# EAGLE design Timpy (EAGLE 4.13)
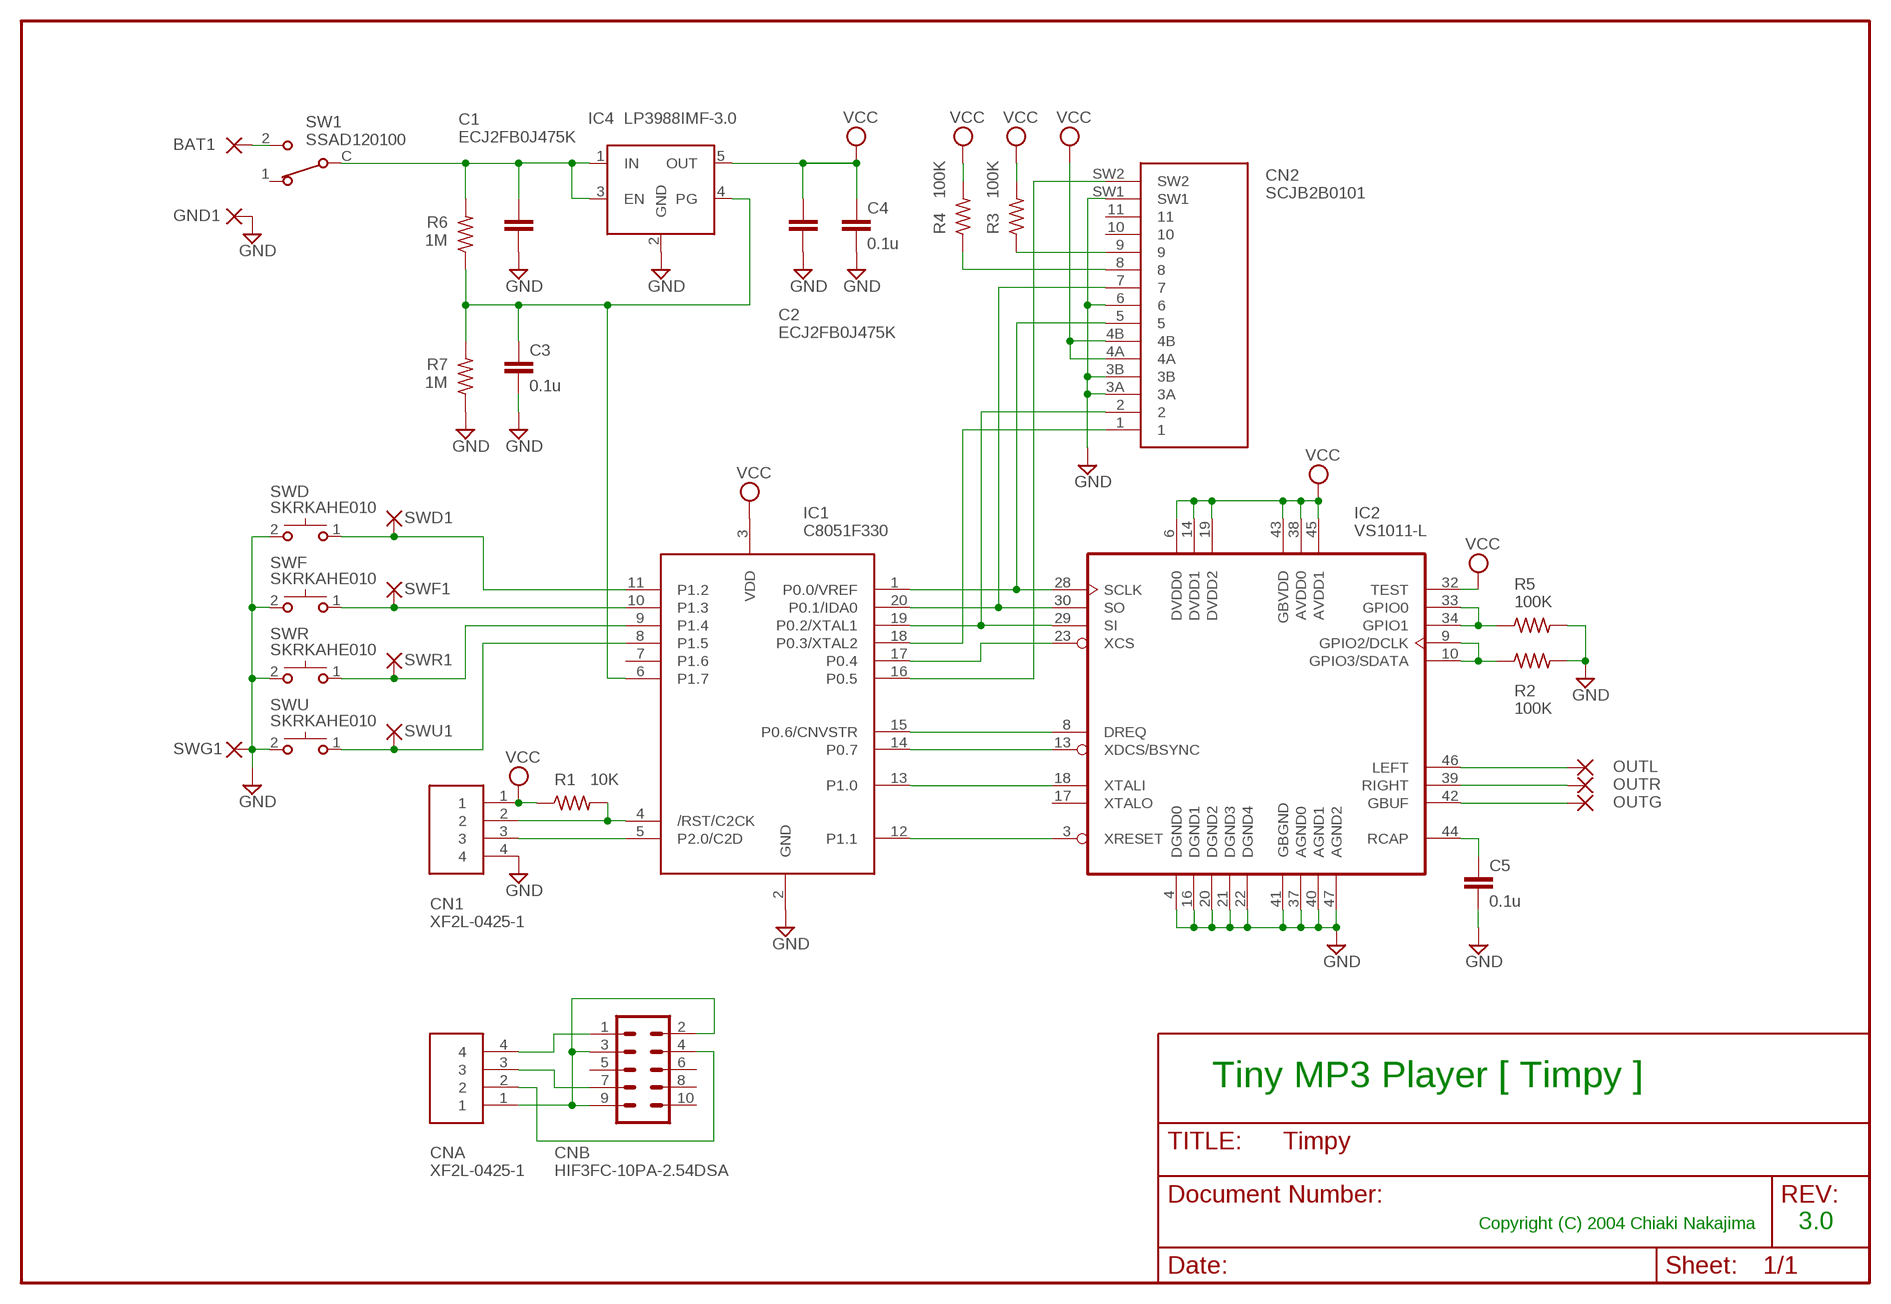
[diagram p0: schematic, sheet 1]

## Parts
BAT1  0.6/0.45  [0.6/0.45]
C1  ECJ2FB0J475K  C-EUC2012  [C2012]
C2  ECJ2FB0J475K  C-EUC2012  [C2012]
C3  0.1u  C-EUC1005  [C1005]
C4  0.1u  C-EUC1005  [C1005]
C5  0.1u  C-EUC1005  [C1005]
CN1  XF2L-0425-1  [XF2L-0425-1]
CN2  SCJB2B0101  SCJB2B010X  [SCJB2B010X]
CNA  XF2L-0425-1  [XF2L-0425-1]
CNB  HIF3FC-10PA-2.54DSA  ML10  [ML10]
GND1  0.6/0.45  [0.6/0.45]
IC1  C8051F330  C8051F33X-LARGE-PROTRUSION  [MLP20-LARGE-PROTRUSION]
IC2  VS1011-L  VS1011-LQFP48  [LQFP-48]
IC4  LP3988IMF-3.0  LP3988  [SOT23-5]
OUTG  0.6/0.45  [0.6/0.45]
OUTL  0.6/0.45  [0.6/0.45]
OUTR  0.6/0.45  [0.6/0.45]
R1  10K  R-US_R1005  [R1005]
R2  100K  R-US_R1005  [R1005]
R3  100K  R-US_R1005  [R1005]
R4  100K  R-US_R1005  [R1005]
R5  100K  R-US_R1005  [R1005]
R6  1M  R-US_R1005  [R1005]
R7  1M  R-US_R1005  [R1005]
SW1  SSAD120100  [SSAD120100]
SWD  SKRKAHE010  [SKRKAHE010]
SWD1  0.6/0.45  [0.6/0.45]
SWF  SKRKAHE010  [SKRKAHE010]
SWF1  0.6/0.45  [0.6/0.45]
SWG1  0.6/0.45  [0.6/0.45]
SWR  SKRKAHE010  [SKRKAHE010]
SWR1  0.6/0.45  [0.6/0.45]
SWU  SKRKAHE010  [SKRKAHE010]
SWU1  0.6/0.45  [0.6/0.45]

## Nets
BATTERY-PAD [Power]: BAT1.P$1(P) SW1.2
GND: C1.2 C2.2 C3.2 C4.2 C5.2 CN1.4 CN2.3A CN2.3B CN2.6 CN2.SW1 GND1.P$1(P) IC1.2(GND) IC2.4(DGND0) IC2.16(DGND1) IC2.20(DGND2) IC2.21(DGND3) IC2.22(DGND4) IC2.37(AGND0) IC2.40(AGND1) IC2.41(GBGND) IC2.47(AGND2) IC4.2(GND) R2.2 R5.2 R7.1 SWD.2 SWF.2 SWG1.P$1(P) SWR.2 SWU.2
N$1: CN1.3 IC1.5(P2.0/C2D)
N$2: IC1.8(P1.5) SWU1.P$1(P) SWU.1
N$3: CN1.2 IC1.4(/RST/C2CK) R1.2
N$4: CN2.9 R3.1
N$5: CN2.8 R4.1
N$6: CN2.5 IC1.1(P0.0/VREF) IC2.28(SCLK)
N$7: IC2.9(GPIO2/DCLK) IC2.10(GPIO3/SDATA) R2.1
N$8: CN2.7 IC1.20(P0.1/IDA0) IC2.30(SO)
N$9: CN2.2 IC1.19(P0.2/XTAL1) IC2.29(SI)
N$10: CN2.1 IC1.18(P0.3/XTAL2)
N$11: IC1.17(P0.4) IC2.23(XCS)
N$12: IC1.15(P0.6/CNVSTR) IC2.8(DREQ)
N$13: IC1.14(P0.7) IC2.13(XDCS/BSYNC)
N$14: IC1.13(P1.0) IC2.18(XTALI)
N$15: IC1.12(P1.1) IC2.3(XRESET)
N$16: IC2.33(GPIO0) IC2.34(GPIO1) R5.1
N$17 [Analog Out]: IC2.46(LEFT) OUTL.P$1(P)
N$18 [Analog Out]: IC2.39(RIGHT) OUTR.P$1(P)
N$19: C3.1 IC1.6(P1.7) IC4.4(PG) R6.1 R7.2
N$20: C5.1 IC2.44(RCAP)
N$21: CN2.SW2 IC1.16(P0.5)
N$22: C1.1 IC4.1(IN) IC4.3(EN) R6.2 SW1.C
N$23 [Analog Out]: IC2.42(GBUF) OUTG.P$1(P)
N$24: IC1.9(P1.4) SWR1.P$1(P) SWR.1
N$25: IC1.10(P1.3) SWF1.P$1(P) SWF.1
N$26: IC1.11(P1.2) SWD1.P$1(P) SWD.1
N$27: CNA.4 CNB.1
N$28: CNA.3 CNB.7
N$29: CNA.2 CNB.4
N$32: CNA.1 CNB.2 CNB.3 CNB.9
VCC: C2.1 C4.1 CN1.1 CN2.4A CN2.4B IC1.3(VDD) IC2.6(DVDD0) IC2.14(DVDD1) IC2.19(DVDD2) IC2.32(TEST) IC2.38(AVDD0) IC2.43(GBVDD) IC2.45(AVDD1) IC4.5(OUT) R1.1 R3.2 R4.2
Unconnected: CN2.10 CN2.11 CNB.5 CNB.6 CNB.8 CNB.10 IC1.7(P1.6) IC2.17(XTALO) SW1.1

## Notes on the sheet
- Tiny MP3 Player [ Timpy ]
- Copyright (C) 2004 Chiaki Nakajima | 3.0

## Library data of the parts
BAT1 GND1 OUTG OUTL OUTR SWD1 SWF1 SWG1 SWR1 SWU1 = pads:0.6/0.45: 0.6mm/0.45mm Through-Hole Pad
C1-C5 = rcl:C-EU: CAPACITOR, European symbol
CN1 CNA = conn-omron-xf2l:XF2L-0425-1: 4P
CN2 = conn-alps-miniSD:SCJB2B010X: SCJB2B0101/2 miniSD connector
CNB = con-harting-ml:ML10: HARTING
IC1 = cygnal_33x:C8051F33X-LARGE-PROTRUSION: Cygnal C8051F330/1 microcontroller with large protrusion pads (for hand soldering)
IC2 = vs10x1-lqfp:VS1011-LQFP48: VS1011 MP3 Decoder (LQFP-48)
IC4 = lp3988:LP3988: National Semiconductor LP3988 Jul 07, 2004 Chiaki Nakajima http://www.chiaki.cc chi@chiaki.cc
R1-R7 = rcl:R-US_: RESISTOR, American symbol
SW1 = switch-alps-tact:SSAD120100: Slide Switch SPDT SSAD120100
SWD SWF SWR SWU = switch-alps:SKRKAHE010: Tact Switch SKRKAHE010

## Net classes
0 default: width 0.15 mm
1 Analog Out: width 0.3 mm
2 Power: width 0.5 mm

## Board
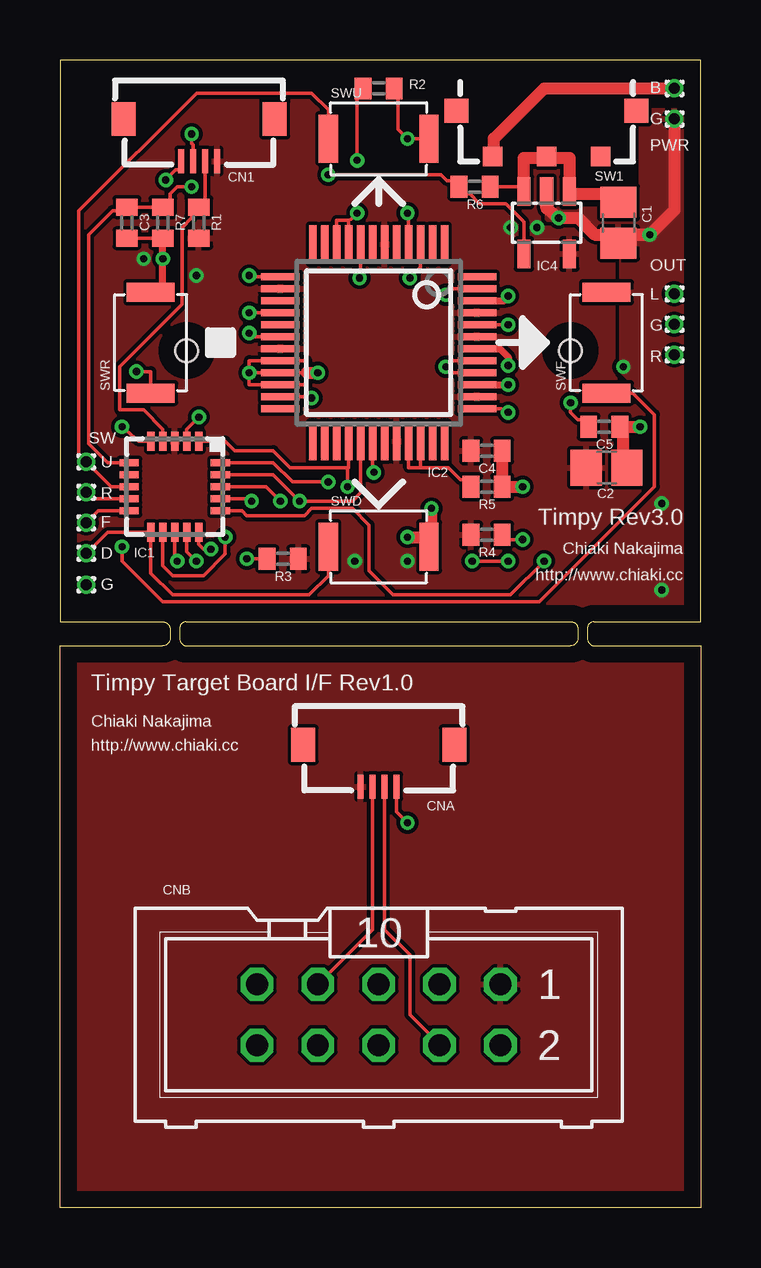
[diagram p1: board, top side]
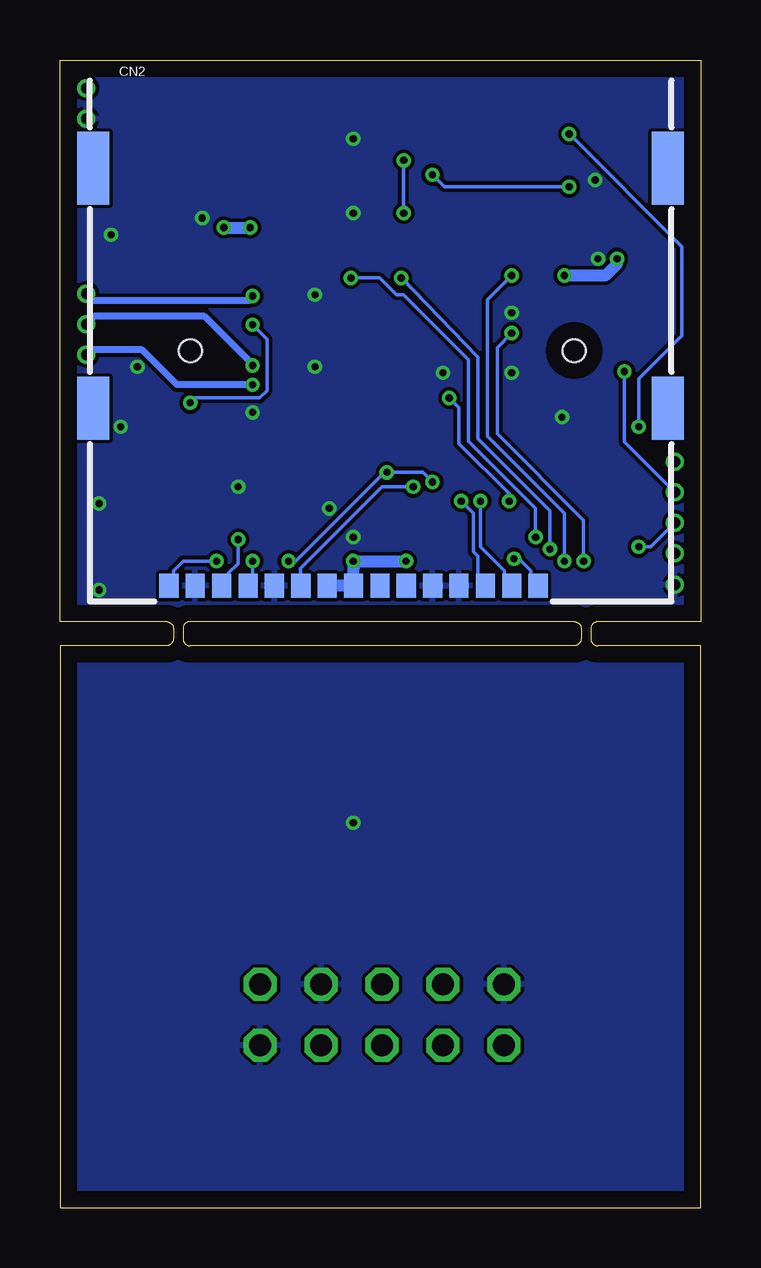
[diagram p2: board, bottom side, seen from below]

Size 26.72 x 47.82 mm. Coordinates in mm from the lower left corner, seen from the top.
Outline: 0,24.41 4.29,24.41 arc-90 4.59,24.11 4.59,23.71 arc-90 4.29,23.41 0,23.41 0,0 26.72,0 26.72,23.41 22.29,23.41 arc-90 21.99,23.71 21.99,24.14 arc-90 22.26,24.41 26.72,24.41 26.72,47.82 0,47.82 0,24.41
Outline: 5.29,23.41 21.29,23.41 arc90 21.59,23.71 21.59,24.14 arc90 21.32,24.41 5.26,24.41 arc90 4.99,24.14 4.99,23.71 arc90 5.29,23.41
Copper layers (1*16): Top 0.035mm / dielectric 1.5mm / Bottom 0.035mm
Design rules "p-ban_min": minimum track width 0.15mm, minimum drill 0.3mm, track to track 0.15mm, track to pad 0.15mm, pad to pad 0.15mm, via to via 0.15mm, smd to smd 0.15mm, copper to edge 0.7mm, drill to drill 0.45mm, minimum pad ring 0.15mm, minimum via ring 0.15mm, stop-mask expansion 4mil, vias tented up to drill 0mil, thermal gap 0.15mm

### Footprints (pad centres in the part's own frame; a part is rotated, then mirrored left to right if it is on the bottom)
0.6/0.45 = drill 0.45 pad 0.6 round: P$1 0,0
C2012 = smd 1.3 x 1.5: 1 -0.85,0; 2 0.85,0
C1005 = smd 0.7 x 0.9: 1 -0.65,0; 2 0.65,0
XF2L-0425-1 = smd 0.25 x 1: 1 -0.75,0.5; 2 -0.25,0.5; 3 0.25,0.5; 4 0.75,0.5 | smd 1 x 1.4: F1 -3.15,-1.25; F2 3.15,-1.25
SCJB2B010X = smd 0.8 x 1: 1 -6.35,0; 2 -5.25,0; 3A -4.15,0; 3B -3.05,0; 4A 0.25,0; 4B 1.35,0; 5 2.45,0; 6 3.55,0; 7 4.65,0; 8 5.75,0; 9 -7.45,0; 10 -1.95,0; 11 -0.85,0; SW1 6.85,0; SW2 7.95,0 | smd 1.35 x 2.6: F1 -12.85,-7.4; F2 11.1,-7.4 | smd 1.35 x 3: F3 -12.85,-17.4; F4 11.1,-17.4 | hole 0.95: 7.05,-9.8; -8.95,-9.8
ML10 = drill 0.914 octagon: 1 -5.08,-1.27; 2 -5.08,1.27; 3 -2.54,-1.27; 4 -2.54,1.27; 5 0,-1.27; 6 0,1.27; 7 2.54,-1.27; 8 2.54,1.27; 9 5.08,-1.27; 10 5.08,1.27
MLP20-LARGE-PROTRUSION = smd 0.8 x 0.3: 1 -1.9,1; 2 -1.9,0.5; 3 -1.9,0; 4 -1.9,-0.5; 5 -1.9,-1; 11 1.9,-1; 12 1.9,-0.5; 13 1.9,0; 14 1.9,0.5; 15 1.9,1 | smd 0.3 x 0.8: 6 -1,-1.9; 7 -0.5,-1.9; 8 0,-1.9; 9 0.5,-1.9; 10 1,-1.9; 16 1,1.9; 17 0.5,1.9; 18 0,1.9; 19 -0.5,1.9; 20 -1,1.9
LQFP-48 = smd 0.3 x 1.6: 1 -2.75,-4.1; 2 -2.25,-4.1; 3 -1.75,-4.1; 4 -1.25,-4.1; 5 -0.75,-4.1; 6 -0.25,-4.1; 7 0.25,-4.1; 8 0.75,-4.1; 9 1.25,-4.1; 10 1.75,-4.1; 11 2.25,-4.1; 12 2.75,-4.1; 25 2.75,4.1; 26 2.25,4.1; 27 1.75,4.1; 28 1.25,4.1; 29 0.75,4.1; 30 0.25,4.1; 31 -0.25,4.1; 32 -0.75,4.1; 33 -1.25,4.1; 34 -1.75,4.1; 35 -2.25,4.1; 36 -2.75,4.1 | smd 1.6 x 0.3: 13 4.1,-2.75; 14 4.1,-2.25; 15 4.1,-1.75; 16 4.1,-1.25; 17 4.1,-0.75; 18 4.1,-0.25; 19 4.1,0.25; 20 4.1,0.75; 21 4.1,1.25; 22 4.1,1.75; 23 4.1,2.25; 24 4.1,2.75; 37 -4.1,2.75; 38 -4.1,2.25; 39 -4.1,1.75; 40 -4.1,1.25; 41 -4.1,0.75; 42 -4.1,0.25; 43 -4.1,-0.25; 44 -4.1,-0.75; 45 -4.1,-1.25; 46 -4.1,-1.75; 47 -4.1,-2.25; 48 -4.1,-2.75
SOT23-5 = smd 0.55 x 1.2: 1 -0.95,-1.3; 2 0,-1.3; 3 0.95,-1.3; 4 0.95,1.3; 5 -0.95,1.3
R1005 = smd 0.7 x 0.9: 1 -0.65,0; 2 0.65,0
SSAD120100 = smd 0.8 x 0.8: 1 -2.25,1.9; 2 2.25,1.9; C 0,1.9 | smd 1 x 1: F1 -3.75,0; F2 3.75,0
SKRKAHE010 = smd 0.8 x 2: 1 -2.1,0; 2 2.1,0

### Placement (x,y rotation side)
BAT1  25.62,46.64 0 top
C1  23.29,41.04 270 top
C2  22.79,30.84 0 top
C3  2.79,41.04 270 top
C4  17.79,31.54 0 top
C5  22.69,32.54 0 top
CN1  5.8,44.11 180 top
CN2  14.23,25.91 180 bottom
CNA  13.29,18.04 180 top
CNB  13.29,8.04 180 top
GND1  25.62,45.37 0 top
IC1  4.79,30.04 270 top
IC2  13.29,36.04 180 top
IC4  20.29,41.04 180 top
OUTG  25.62,36.81 0 top
OUTL  25.62,38.08 0 top
OUTR  25.62,35.54 0 top
R1  5.79,41.04 90 top
R2  13.29,46.64 0 top
R3  9.29,27.04 0 top
R4  17.79,28.04 180 top
R5  17.79,30.04 0 top
R6  17.29,42.54 0 top
R7  4.29,41.04 90 top
SW1  20.29,45.7 180 top
SWD  13.29,27.54 0 top
SWD1  1.09,27.27 0 top
SWF  22.79,36.04 90 top
SWF1  1.09,28.54 0 top
SWG1  1.09,25.96 0 top
SWR  3.79,36.04 90 top
SWR1  1.09,29.81 0 top
SWU  13.29,44.54 0 top
SWU1  1.09,31.08 0 top

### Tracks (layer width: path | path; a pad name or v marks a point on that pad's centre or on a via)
BATTERY-PAD
  Top 0.5: BAT1.P$1 20.19,46.64 18.09,44.54 18.09,43.84 SW1.2
GND  (via drill 0.3 pad 0.6)
  Top 0.15: IC1.2 5.29,32.44 v5.79,32.94 | R7.1 C3.2 | IC2.16 v7.89,37.29 | v7.89,34.79 7.89,34.29 IC2.22 10.29,34.29 10.29,34.79 | v7.89,34.79 7.89,35.29 IC2.20 10.29,35.29 10.29,34.79 | v7.89,34.79 IC2.21 10.29,34.79 | 10.29,34.79 10.5,34.79 | 10.77,34.79 v10.75,34.79 | IC2.37 18.39,33.29 v18.69,33.14 | IC2.4 14.54,41.39 v14.49,41.44 | IC2.47 16.34,38.29 v16.09,38.04 | R2.2 14.09,46.39 14.09,44.94 v14.49,44.54 SWU.2 | CN1.4 5.05,43.24 4.83,43.24 v4.41,42.82 | IC2.41 16.34,35.29 v16.09,35.04 16.34,34.79 IC2.40
  Top 0.3: SWR.2 4.29,38.14 v4.29,39.54 R7.1 | C3.2 2.79,40.44 2.99,40.24
  Top 0.5: IC4.2 20.29,41.64 v20.79,41.24 21.59,41.24 22.29,40.54 v24.59,40.54 | v24.59,40.54 23.29,40.54 C1.2 23.24,40.24 23.49,40.24 | SWF.2 23.49,38.24 | v24.59,40.54 25.63,41.58 GND1.P$1 | v19.29,30.04 R5.2 C4.2 | SWD.2 15.49,27.64 v15.49,29.14 | v14.49,27.94 15.29,27.94 | 10.29,34.79 10.77,34.79 | 23.49,32.54 C5.2 | C2.2 23.49,30.99 23.49,32.54 | 23.49,32.54 v24.19,32.54
  other vias: 23.49,35.04 25.09,29.34 25.09,25.74
  pour Bottom: 26.89,47.94 26.89,24.24 -0.11,24.24 -0.11,47.94
  pour Top: 19.09,24.34 26.79,24.34 26.79,45.74 24.19,45.74 24.19,41.64 20.29,41.64 20.29,41.14 21.79,41.14 23.39,39.54 23.39,34.84 24.79,33.44 24.79,30.04
N$1  (via drill 0.3 pad 0.6)
  Top 0.15: IC1.5 3.29,31.94 v2.59,32.54 | CN1.3 5.55,44.28 5.49,44.34 v5.49,44.74
  Bottom 0.15: v2.59,32.54 2.59,34.54 0.79,36.34 0.79,40.04 v5.49,44.74
N$2
  Top 0.15: SWU.1 11.19,45.74 10.49,46.44 5.69,46.44 0.79,41.54 0.79,31.38 SWU1.P$1 2.13,30.04 IC1.8
N$3
  Top 0.15: 5.79,41.64 R1.2 | CN1.2 6.05,41.9 5.79,41.64 | 5.79,41.64 5.49,41.34 5.49,41.24 5.09,40.84 5.09,37.64 2.49,35.04 2.49,33.24 3.49,33.24 4.29,32.44 IC1.4
N$4  (via drill 0.3 pad 0.6)
  Top 0.15: v7.79,27.04 R3.1
  Bottom 0.15: CN2.9 6.78,25.93 7.09,26.24 7.09,26.54 7.59,27.04 v7.79,27.04
N$5  (via drill 0.3 pad 0.6)
  Top 0.15: R4.1 18.69,27.74 18.49,27.84 v19.29,27.84
  Bottom 0.15: CN2.8 19.99,25.94 19.68,26.25 19.68,26.45 19.29,26.84 v19.29,27.84
N$6  (via drill 0.3 pad 0.6)
  Top 0.15: IC1.1 6.89,31.94 7.29,31.54 8.89,31.54 9.59,30.84 11.99,30.84 | IC2.28 12.04,30.84 11.99,30.84 | 11.99,30.84 v11.99,30.04
  Bottom 0.15: CN2.5 16.68,26.63 16.69,26.64 13.29,30.04 v11.99,30.04
N$7  (via drill 0.3 pad 0.6)
  Top 0.15: IC2.10 11.54,41.14 12.04,41.14 | 12.04,41.14 IC2.9 | 12.04,41.14 12.14,41.19 v12.39,41.44 | R2.1 12.59,46.64 12.39,46.44 v12.39,43.64
  Bottom 0.15: v12.39,41.44 v12.39,43.64
N$8  (via drill 0.3 pad 0.6)
  Top 0.15: IC1.20 8.89,31.04 9.69,30.24 v11.19,30.24 | IC2.30 13.04,30.69 v13.09,30.64 | v17.19,26.94 v18.69,26.94
  Bottom 0.15: CN2.7 18.88,25.83 18.69,26.04 v18.69,26.94 | v11.19,30.24 11.59,30.64 v13.09,30.64 13.19,30.64 16.89,26.94 v17.19,26.94
N$9  (via drill 0.3 pad 0.6)
  Top 0.15: IC1.19 8.89,30.54 v9.99,29.44 12.19,29.44 12.54,29.79 IC2.29
  Bottom 0.15: v9.99,29.44 9.49,28.94 9.49,27.34 9.29,27.14 9.29,26.24 8.98,25.93 CN2.2
N$10  (via drill 0.3 pad 0.6)
  Top 0.15: IC1.18 8.59,30.04 v9.19,29.44
  Bottom 0.15: CN2.1 7.88,25.93 8.19,26.14 8.19,26.54 9.19,27.54 v9.19,29.44
N$11  (via drill 0.3 pad 0.6)
  Top 0.15: IC2.23 10.44,33.79 v10.49,33.74 | IC1.17 7.89,29.54 v7.99,29.44
  Bottom 0.15: v10.49,33.74 10.09,33.34 10.09,31.84 7.99,29.74 v7.99,29.44
N$12  (via drill 0.3 pad 0.6)
  Top 0.15: IC2.8 12.54,38.79 v12.49,38.74 | IC1.15 5.79,27.64 5.99,27.44 v6.29,27.44
  Bottom 0.15: v6.29,27.44 6.29,29.04 9.29,32.04 9.29,35.44 v12.49,38.74
N$13  (via drill 0.3 pad 0.6)
  Top 0.15: IC1.14 5.29,27.34 v5.69,26.94 | IC2.13 7.94,38.79 v7.89,38.84
  Bottom 0.15: v5.69,26.94 5.69,28.94 8.89,32.14 8.89,37.84 v7.89,38.84
N$14  (via drill 0.3 pad 0.6)
  Top 0.15: IC1.13 4.79,27.04 v4.89,26.94 | IC2.18 8.04,36.29 v7.89,36.44
  Bottom 0.15: v4.89,26.94 4.89,28.64 8.49,32.24 8.49,35.84 v7.89,36.44
N$15  (via drill 0.3 pad 0.6)
  Top 0.15: 4.29,27.04 IC1.12 4.29,26.74 4.69,26.34 5.99,26.34 6.89,27.24 v6.89,27.94 | IC2.3 15.04,39.19 v14.59,38.74
  Bottom 0.15: v14.59,38.74 13.39,38.74 12.69,38.04 12.39,38.04 9.69,35.34 9.69,31.94 6.89,29.14 v6.89,27.94
N$16
  Top 0.15: IC2.33 14.54,30.84 15.03,30.84 | IC2.34 15.03,30.84 | 15.03,30.84 16.19,30.84 16.69,30.34 16.89,30.34 17.14,30.09 R5.1
N$17  (via drill 0.3 pad 0.6)
  Top 0.3: v18.69,37.99 18.69,37.94 18.54,37.79 IC2.46
  Bottom 0.3: OUTL.P$1 25.34,37.79 18.84,37.79 18.69,37.94 v18.69,37.99
N$18  (via drill 0.3 pad 0.6)
  Top 0.3: IC2.39 v18.69,34.29
  Bottom 0.3: v18.69,34.29 21.84,34.29 23.29,35.74 25.42,35.74 OUTR.P$1
N$19  (via drill 0.3 pad 0.6)
  Top 0.15: IC1.6 1.99,31.04 1.19,31.84 1.19,40.54 2.19,41.54 2.59,41.54 2.79,41.74 C3.1 R7.2 4.29,41.74 4.59,42.04 4.59,42.24 4.89,42.54 v5.49,42.54 | IC4.4 19.34,41.09 18.59,41.84 17.49,41.84 17.09,42.24 16.89,42.24 16.59,42.54 R6.1 16.64,42.59 16.44,42.79 16.14,42.79 15.89,43.04 v11.19,43.04
  Bottom 0.15: v11.19,43.04 10.69,42.54 v5.49,42.54
N$20  (via drill 0.3 pad 0.6)
  Top 0.15: IC2.44 17.41,36.79 v18.69,36.79 | v21.29,33.54 21.29,33.14 21.59,32.84 21.89,32.84 22.14,32.59 C5.1
  Bottom 0.15: v18.69,36.79 18.09,36.19 18.09,34.04 18.39,33.74 21.09,33.74 v21.29,33.54
N$21  (via drill 0.3 pad 0.6)
  Top 0.15: IC1.16 7.59,29.04 7.79,28.84 10.19,28.84 10.49,29.14 12.19,29.14 12.89,28.44 12.89,26.54 13.89,25.54 18.79,25.54 v20.19,26.94
  Bottom 0.15: v20.19,26.94 21.59,26.94 21.99,26.54 21.99,26.14 22.19,25.94 22.18,25.93 CN2.SW2
N$22
  Top 0.15: IC4.3 19.34,42.39 19.19,42.54 R6.2
  Top 0.5: IC4.3 19.34,43.74 20.29,43.74 | 20.29,43.74 SW1.C | 20.29,43.74 21.24,43.74 IC4.1 21.29,42.29 21.29,42.24 22.94,42.24 C1.1
N$23  (via drill 0.3 pad 0.6)
  Top 0.3: v18.69,35.09 18.69,35.44 18.34,35.79 IC2.42
  Bottom 0.3: OUTG.P$1 25.29,37.14 20.69,37.14 18.69,35.14 v18.69,35.09
N$24  (via drill 0.3 pad 0.6)
  Top 0.15: SWR.1 3.79,34.84 v3.19,34.84 | IC1.9 1.36,29.54 SWR1.P$1
  Bottom 0.15: v3.19,34.84 3.19,31.91 SWR1.P$1
N$25  (via drill 0.3 pad 0.6)
  Top 0.15: SWF.1 23.89,33.94 24.79,33.04 24.79,30.04 19.99,25.24 4.29,25.24 2.59,26.94 v2.59,27.54 | IC1.10 1.59,29.04 SWF1.P$1
  Bottom 0.15: v2.59,27.54 2.09,27.54 SWF1.P$1
N$26
  Top 0.15: SWD1.P$1 1.12,27.27 1.99,28.14 IC1.11 3.79,26.44 4.69,25.54 10.39,25.54 11.19,26.34 SWD.1
N$27
  pour Top: -0.11,-0.16 26.89,-0.16 26.89,23.54 -0.11,23.54
N$28
  Top 0.15: CNA.3 13.04,11.59 CNB.7
N$29
  Top 0.15: CNA.2 13.54,11.59 14.59,10.54 14.59,8.04 15.83,6.8 CNB.4
N$32  (via drill 0.3 pad 0.6)
  Top 0.15: CNA.1 14.04,16.49 v14.49,16.04
  pour Bottom (rank 2): -0.11,23.54 26.89,23.54 26.89,-0.16 -0.11,-0.16
VCC  (via drill 0.3 pad 0.6)
  Bottom 0.5: CN2.4B 14.52,25.91 14.49,25.94 14.48,25.93 CN2.4A 14.48,26.65 v14.49,26.94 v12.29,26.94 | v3.49,39.54 3.49,39.34 3.99,38.84 v5.69,38.84 | v19.89,40.84 v18.79,40.84
  pour Top (rank 2): 26.89,47.94 26.89,24.24 -0.11,24.24 -0.11,47.94

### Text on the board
tNames: B | G | PWR | OUT | L | G | R | SW | U | R | Timpy Rev3.0 | F | Chiaki Nakajima | D | http://www.chiaki.cc | G | Timpy Target Board I/F Rev1.0 | Chiaki Nakajima | http://www.chiaki.cc
Measures: 23.41 | 23.41 | 26.72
